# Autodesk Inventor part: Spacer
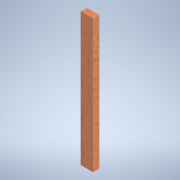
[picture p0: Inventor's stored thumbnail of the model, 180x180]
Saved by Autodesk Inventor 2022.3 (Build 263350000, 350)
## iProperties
Created: 2022-05
Part Number: Spacer
Material: Wood (Oak)
Document SubType Name: Modeling
Designer: elimb
Density: 0.76 g/cm^3
Appearance: White Oak - Natural Medium Gloss
Author: elimb
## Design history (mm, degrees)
sketch "Sketch1"
  geometry: L1 (-6.35, -67.31)-(6.35, -67.31); L2 (6.35, -67.31)-(6.35, 67.31); L3 (6.35, 67.31)-(-6.35, 67.31); L4 (-6.35, 67.31)-(-6.35, -67.31); L5 (-6.35, -67.31)-(6.35, 67.31); L6 (6.35, -67.31)-(-6.35, 67.31); 1 further point
  constraints: 12 end point, 2 midpoint, 2 parallel, 1 horizontal, 1 perpendicular
  dimensions: "d0" = 12.7 distance of L3.end L2.end
extrude "Extrusion1" new body sketch "Sketch1" distance "d2" = 6.35; taper "d3" = 0 deg
body "Solid1"
